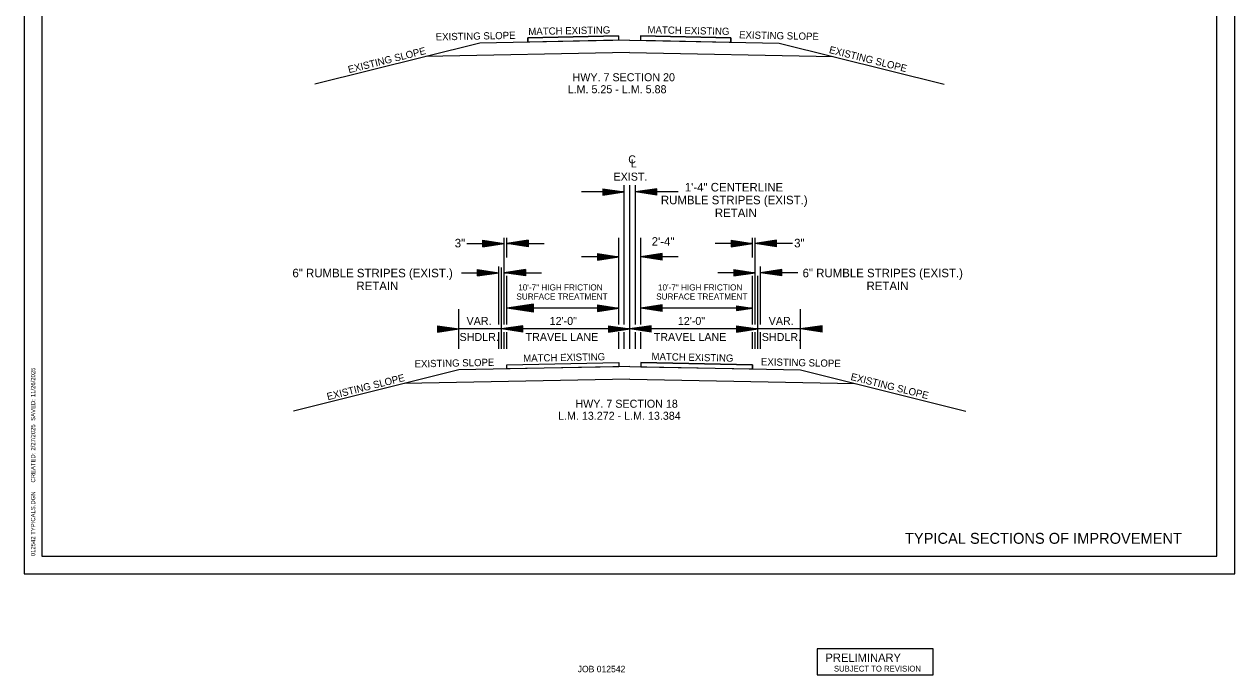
# Model space of a CAD drawing. Extents: x 34757 to 38214, y 51436 to 59430.
# Drawn here: x 34757 to 36457, y 53228 to 54141 of the extents above; entities that cross this region are included whole.
import ezdxf

# ---------------------------------------------------------------- set-up
doc = ezdxf.new("R2010")
doc.units = 0
for name, color, linetype in [('Default', 7, 'Continuous'), ('DSN_DRFT_Junk-No-Plot', 7, 'Continuous'), ('R_Draft', 7, 'Continuous'), ('SHET_Border-Lines', 7, 'Continuous'), ('SHET_Border-Text', 7, 'Continuous')]:
    doc.layers.add(name, color=color, linetype=linetype)

msp = doc.modelspace()

# ---------------------------------------------------------------- linework, layer by layer
at = {"layer": 'Default'}
for p, q in [((35396.6, 54114.9), (35164.6, 54056.9)), ((35606.6, 54119.1), (35396.6, 54114.9)), ((35591.1, 54124.8), (35464.1, 54122.3)), ((35464.1, 54122.3), (35464.1, 54116.3)), ((35606.6, 54119.1), (35816.6, 54114.9)), ((35622.1, 54124.8), (35749.1, 54122.3)), ((35749.1, 54122.3), (35749.1, 54116.3)), ((35816.6, 54114.9), (36048.6, 54056.9)), ((35606.6, 54101.6), (35320.5, 54095.9)), ((35606.6, 54101.6), (35892.7, 54095.9)), ((35569, 53910.4), (35599, 53905.9)), ((35569, 53910.4), (35569, 53901.4)), ((35569, 53909.6), (35594, 53905.9)), ((35569, 53908.8), (35588.8, 53905.9)), ((35569, 53908.1), (35583.8, 53905.9)), ((35569, 53907.3), (35578.7, 53905.9)), ((35599, 53831.9), (35599, 53915.4)), ((35607, 53862.8), (35607, 53915.4)), ((35615, 53831.9), (35615, 53915.4)), ((35645, 53910.4), (35615, 53905.9)), ((35645, 53909.6), (35620, 53905.9)), ((35645, 53908.8), (35625.1, 53905.9)), ((35645, 53908.1), (35630.1, 53905.9)), ((35645, 53907.3), (35635.2, 53905.9)), ((35645, 53901.4), (35645, 53910.4)), ((35599, 53905.9), (35539, 53905.9)), ((35569, 53906.6), (35573.7, 53905.9)), ((35569, 53901.4), (35599, 53905.9)), ((35569, 53904.4), (35578.7, 53905.9)), ((35569, 53902.9), (35588.8, 53905.9)), ((35569, 53902.1), (35594, 53905.9)), ((35569, 53903.6), (35583.8, 53905.9)), ((35569, 53905.1), (35573.7, 53905.9)), ((35645, 53901.4), (35615, 53905.9)), ((35675, 53905.9), (35615, 53905.9)), ((35645, 53902.1), (35620, 53905.9)), ((35645, 53902.9), (35625.1, 53905.9)), ((35645, 53903.6), (35630.1, 53905.9)), ((35645, 53904.4), (35635.2, 53905.9)), ((35645, 53906.6), (35640.2, 53905.9)), ((35645, 53905.1), (35640.2, 53905.9)), ((35607, 53685.5), (35607, 53862.8)), ((35430.7, 53719.7), (35430.7, 53841.5)), ((35434.5, 53813.8), (35434.5, 53841.5)), ((35591.5, 53719.7), (35591.5, 53841.5)), ((35622.5, 53719.7), (35622.5, 53841.5)), ((35779.5, 53813.8), (35779.5, 53841.5)), ((35783.2, 53719.7), (35783.2, 53841.5)), ((35378.2, 53833.5), (35430.7, 53833.5)), ((35400.7, 53838), (35430.7, 53833.5)), ((35400.7, 53829), (35400.7, 53838)), ((35400.7, 53837.2), (35425.7, 53833.5)), ((35400.7, 53836.5), (35420.5, 53833.5)), ((35400.7, 53835.7), (35415.5, 53833.5)), ((35400.7, 53834.9), (35410.5, 53833.5)), ((35400.7, 53834.2), (35405.5, 53833.5)), ((35400.7, 53829), (35430.7, 53833.5)), ((35400.7, 53832), (35410.5, 53833.5)), ((35400.7, 53830.5), (35420.5, 53833.5)), ((35400.7, 53829.7), (35425.7, 53833.5)), ((35400.7, 53831.2), (35415.5, 53833.5)), ((35400.7, 53832.8), (35405.5, 53833.5)), ((35464.5, 53838), (35434.5, 53833.5)), ((35464.5, 53829), (35434.5, 53833.5)), ((35434.5, 53833.5), (35487, 53833.5)), ((35464.5, 53837.2), (35439.5, 53833.5)), ((35464.5, 53829.7), (35439.5, 53833.5)), ((35464.5, 53836.5), (35444.6, 53833.5)), ((35464.5, 53830.5), (35444.6, 53833.5)), ((35464.5, 53835.7), (35449.6, 53833.5)), ((35464.5, 53831.2), (35449.6, 53833.5)), ((35464.5, 53834.9), (35454.7, 53833.5)), ((35464.5, 53832), (35454.7, 53833.5)), ((35464.5, 53834.2), (35459.7, 53833.5)), ((35464.5, 53832.8), (35459.7, 53833.5)), ((35464.5, 53838), (35464.5, 53829)), ((35599, 53719.7), (35599, 53831.9)), ((35615, 53719.7), (35615, 53831.9)), ((35779.5, 53833.5), (35727, 53833.5)), ((35749.5, 53838), (35779.5, 53833.5)), ((35749.5, 53838), (35749.5, 53829)), ((35749.5, 53837.2), (35774.5, 53833.5)), ((35749.5, 53836.5), (35769.3, 53833.5)), ((35749.5, 53835.7), (35764.3, 53833.5)), ((35749.5, 53834.9), (35759.2, 53833.5)), ((35749.5, 53834.2), (35754.2, 53833.5)), ((35749.5, 53829), (35779.5, 53833.5)), ((35749.5, 53832), (35759.2, 53833.5)), ((35749.5, 53830.5), (35769.3, 53833.5)), ((35749.5, 53829.7), (35774.5, 53833.5)), ((35749.5, 53831.2), (35764.3, 53833.5)), ((35749.5, 53832.8), (35754.2, 53833.5)), ((35813.2, 53838), (35783.2, 53833.5)), ((35835.7, 53833.5), (35783.2, 53833.5)), ((35813.2, 53829), (35783.2, 53833.5)), ((35813.2, 53837.2), (35788.2, 53833.5)), ((35813.2, 53829.7), (35788.2, 53833.5)), ((35813.2, 53836.5), (35793.4, 53833.5)), ((35813.2, 53830.5), (35793.4, 53833.5)), ((35813.2, 53835.7), (35798.4, 53833.5)), ((35813.2, 53831.2), (35798.4, 53833.5)), ((35813.2, 53834.9), (35803.5, 53833.5)), ((35813.2, 53832), (35803.5, 53833.5)), ((35813.2, 53834.2), (35808.5, 53833.5)), ((35813.2, 53832.8), (35808.5, 53833.5)), ((35813.2, 53829), (35813.2, 53838)), ((35591.5, 53814.7), (35539, 53814.7)), ((35561.5, 53819.2), (35591.5, 53814.7)), ((35561.5, 53819.2), (35561.5, 53810.2)), ((35561.5, 53818.4), (35586.5, 53814.7)), ((35561.5, 53817.7), (35581.3, 53814.7)), ((35561.5, 53816.9), (35576.3, 53814.7)), ((35561.5, 53816.1), (35571.2, 53814.7)), ((35561.5, 53815.4), (35566.2, 53814.7)), ((35561.5, 53810.2), (35591.5, 53814.7)), ((35561.5, 53813.2), (35571.2, 53814.7)), ((35561.5, 53811.7), (35581.3, 53814.7)), ((35561.5, 53810.9), (35586.5, 53814.7)), ((35561.5, 53812.5), (35576.3, 53814.7)), ((35561.5, 53814), (35566.2, 53814.7)), ((35652.5, 53819.2), (35622.5, 53814.7)), ((35675, 53814.7), (35622.5, 53814.7)), ((35652.5, 53810.2), (35622.5, 53814.7)), ((35652.5, 53818.4), (35627.5, 53814.7)), ((35652.5, 53810.9), (35627.5, 53814.7)), ((35652.5, 53817.7), (35632.6, 53814.7)), ((35652.5, 53811.7), (35632.6, 53814.7)), ((35652.5, 53816.9), (35637.6, 53814.7)), ((35652.5, 53812.5), (35637.6, 53814.7)), ((35652.5, 53816.2), (35642.7, 53814.7)), ((35652.5, 53813.2), (35642.7, 53814.7)), ((35652.5, 53815.4), (35647.7, 53814.7)), ((35652.5, 53814), (35647.7, 53814.7)), ((35652.5, 53810.2), (35652.5, 53819.2)), ((35370.7, 53792.4), (35423.2, 53792.4)), ((35393.2, 53796.9), (35423.2, 53792.4)), ((35393.2, 53787.9), (35393.2, 53796.9)), ((35393.2, 53796.2), (35418.2, 53792.4)), ((35393.2, 53795.4), (35413, 53792.4)), ((35393.2, 53794.7), (35408, 53792.4)), ((35393.2, 53793.9), (35403, 53792.4)), ((35393.2, 53793.1), (35398, 53792.4)), ((35393.2, 53787.9), (35423.2, 53792.4)), ((35393.2, 53791), (35403, 53792.4)), ((35393.2, 53789.5), (35413, 53792.4)), ((35393.2, 53788.7), (35418.2, 53792.4)), ((35393.2, 53790.2), (35408, 53792.4)), ((35393.2, 53791.7), (35398, 53792.4)), ((35423.2, 53719.7), (35423.2, 53801)), ((35427, 53685.5), (35427, 53799.9)), ((35427, 53685.5), (35427, 53788)), ((35460.7, 53796.9), (35430.7, 53792.4)), ((35460.7, 53787.9), (35430.7, 53792.4)), ((35430.7, 53792.4), (35483.2, 53792.4)), ((35434.5, 53719.7), (35434.5, 53788.2)), ((35460.7, 53796.2), (35435.7, 53792.4)), ((35460.7, 53788.7), (35435.7, 53792.4)), ((35460.7, 53795.4), (35440.9, 53792.4)), ((35460.7, 53789.5), (35440.9, 53792.4)), ((35460.7, 53794.7), (35445.9, 53792.4)), ((35460.7, 53790.2), (35445.9, 53792.4)), ((35460.7, 53793.9), (35451, 53792.4)), ((35460.7, 53791), (35451, 53792.4)), ((35460.7, 53793.1), (35456, 53792.4)), ((35460.7, 53791.7), (35456, 53792.4)), ((35460.7, 53796.9), (35460.7, 53787.9)), ((35783.2, 53792.4), (35730.7, 53792.4)), ((35753.2, 53796.9), (35783.2, 53792.4)), ((35753.2, 53796.9), (35753.2, 53787.9)), ((35753.2, 53796.2), (35778.2, 53792.4)), ((35753.2, 53795.4), (35773, 53792.4)), ((35753.2, 53794.7), (35768, 53792.4)), ((35753.2, 53793.9), (35763, 53792.4)), ((35753.2, 53793.1), (35758, 53792.4)), ((35753.2, 53787.9), (35783.2, 53792.4)), ((35753.2, 53791), (35763, 53792.4)), ((35753.2, 53789.5), (35773, 53792.4)), ((35753.2, 53788.7), (35778.2, 53792.4)), ((35753.2, 53790.2), (35768, 53792.4)), ((35753.2, 53791.7), (35758, 53792.4)), ((35779.5, 53719.7), (35779.5, 53788.2)), ((35787, 53685.5), (35787, 53788)), ((35790.7, 53719.7), (35790.7, 53801)), ((35820.7, 53796.9), (35790.7, 53792.4)), ((35820.7, 53787.9), (35790.7, 53792.4)), ((35843.2, 53792.4), (35790.7, 53792.4)), ((35820.7, 53796.2), (35795.7, 53792.4)), ((35820.7, 53788.7), (35795.7, 53792.4)), ((35820.7, 53795.4), (35800.9, 53792.4)), ((35820.7, 53789.5), (35800.9, 53792.4)), ((35820.7, 53794.7), (35805.9, 53792.4)), ((35820.7, 53790.2), (35805.9, 53792.4)), ((35820.7, 53793.9), (35811, 53792.4)), ((35820.7, 53791), (35811, 53792.4)), ((35820.7, 53793.1), (35816, 53792.4)), ((35820.7, 53791.7), (35816, 53792.4)), ((35820.7, 53787.9), (35820.7, 53796.9)), ((35367, 53685.5), (35367, 53741.5)), ((35472, 53748.3), (35434.5, 53742.7)), ((35591.5, 53742.7), (35434.5, 53742.7)), ((35472, 53737), (35434.5, 53742.7)), ((35472, 53747.4), (35440.7, 53742.7)), ((35472, 53738), (35440.7, 53742.7)), ((35472, 53746.4), (35447.2, 53742.7)), ((35472, 53738.9), (35447.2, 53742.7)), ((35472, 53745.5), (35453.4, 53742.7)), ((35472, 53739.9), (35453.4, 53742.7)), ((35472, 53744.5), (35459.8, 53742.7)), ((35472, 53740.9), (35459.8, 53742.7)), ((35472, 53743.6), (35466, 53742.7)), ((35472, 53741.8), (35466, 53742.7)), ((35472, 53737), (35472, 53748.3)), ((35561.5, 53747.2), (35591.5, 53742.7)), ((35561.5, 53747.2), (35561.5, 53738.2)), ((35561.5, 53746.4), (35586.5, 53742.7)), ((35561.5, 53745.7), (35581.3, 53742.7)), ((35561.5, 53744.9), (35576.3, 53742.7)), ((35561.5, 53744.1), (35571.2, 53742.7)), ((35561.5, 53743.4), (35566.2, 53742.7)), ((35561.5, 53738.2), (35591.5, 53742.7)), ((35561.5, 53741.2), (35571.2, 53742.7)), ((35561.5, 53739.7), (35581.3, 53742.7)), ((35561.5, 53738.9), (35586.5, 53742.7)), ((35561.5, 53740.4), (35576.3, 53742.7)), ((35561.5, 53742), (35566.2, 53742.7)), ((35652.5, 53747.2), (35622.5, 53742.7)), ((35779.5, 53742.7), (35622.5, 53742.7)), ((35652.5, 53738.2), (35622.5, 53742.7)), ((35652.5, 53746.4), (35627.5, 53742.7)), ((35652.5, 53738.9), (35627.5, 53742.7)), ((35652.5, 53745.7), (35632.6, 53742.7)), ((35652.5, 53739.7), (35632.6, 53742.7)), ((35652.5, 53744.9), (35637.6, 53742.7)), ((35652.5, 53740.4), (35637.6, 53742.7)), ((35652.5, 53744.1), (35642.7, 53742.7)), ((35652.5, 53741.2), (35642.7, 53742.7)), ((35652.5, 53743.4), (35647.7, 53742.7)), ((35652.5, 53742), (35647.7, 53742.7)), ((35652.5, 53738.2), (35652.5, 53747.2)), ((35757, 53746), (35779.5, 53742.7)), ((35757, 53746), (35757, 53739.3)), ((35757, 53745.5), (35775.7, 53742.7)), ((35757, 53744.9), (35771.8, 53742.7)), ((35757, 53744.3), (35768.1, 53742.7)), ((35757, 53743.8), (35764.3, 53742.7)), ((35757, 53743.2), (35760.5, 53742.7)), ((35757, 53739.3), (35779.5, 53742.7)), ((35757, 53741.6), (35764.3, 53742.7)), ((35757, 53740.4), (35771.8, 53742.7)), ((35757, 53739.9), (35775.7, 53742.7)), ((35757, 53741), (35768.1, 53742.7)), ((35757, 53742.1), (35760.5, 53742.7)), ((35847, 53685.5), (35847, 53741.5)), ((35337, 53718), (35367, 53713.5)), ((35337, 53718), (35337, 53709)), ((35337, 53717.2), (35362, 53713.5)), ((35337, 53716.5), (35356.8, 53713.5)), ((35337, 53715.7), (35351.8, 53713.5)), ((35337, 53714.9), (35346.7, 53713.5)), ((35337, 53714.2), (35341.7, 53713.5)), ((35337, 53709), (35367, 53713.5)), ((35337, 53712), (35346.7, 53713.5)), ((35337, 53710.5), (35356.8, 53713.5)), ((35337, 53709.7), (35362, 53713.5)), ((35337, 53711.2), (35351.8, 53713.5)), ((35337, 53712.8), (35341.7, 53713.5)), ((35427, 53713.5), (35367, 53713.5)), ((35423.2, 53685.5), (35423.2, 53709.1)), ((35457, 53718), (35427, 53713.5)), ((35607, 53713.5), (35427, 53713.5)), ((35457, 53709), (35427, 53713.5)), ((35430.7, 53685.5), (35430.7, 53709.1)), ((35457, 53717.2), (35432, 53713.5)), ((35457, 53709.7), (35432, 53713.5)), ((35434.5, 53685.5), (35434.5, 53709.1)), ((35457, 53716.5), (35437.1, 53713.5)), ((35457, 53710.5), (35437.1, 53713.5)), ((35457, 53715.7), (35442.1, 53713.5)), ((35457, 53711.2), (35442.1, 53713.5)), ((35457, 53714.9), (35447.2, 53713.5)), ((35457, 53712), (35447.2, 53713.5)), ((35457, 53714.2), (35452.2, 53713.5)), ((35457, 53712.8), (35452.2, 53713.5)), ((35457, 53709), (35457, 53718)), ((35577, 53718), (35607, 53713.5)), ((35577, 53718), (35577, 53709)), ((35577, 53717.2), (35602, 53713.5)), ((35577, 53716.5), (35596.8, 53713.5)), ((35577, 53715.7), (35591.8, 53713.5)), ((35577, 53714.9), (35586.7, 53713.5)), ((35577, 53714.2), (35581.7, 53713.5)), ((35577, 53709), (35607, 53713.5)), ((35577, 53712), (35586.7, 53713.5)), ((35577, 53710.5), (35596.8, 53713.5)), ((35577, 53709.7), (35602, 53713.5)), ((35577, 53711.2), (35591.8, 53713.5)), ((35577, 53712.8), (35581.7, 53713.5)), ((35591.5, 53685.5), (35591.5, 53709.1)), ((35599, 53685.5), (35599, 53709.1)), ((35637, 53718), (35607, 53713.5)), ((35787, 53713.5), (35607, 53713.5)), ((35637, 53709), (35607, 53713.5)), ((35637, 53717.2), (35612, 53713.5)), ((35637, 53709.7), (35612, 53713.5)), ((35615, 53685.5), (35615, 53709.1)), ((35637, 53716.5), (35617.1, 53713.5)), ((35637, 53710.5), (35617.1, 53713.5)), ((35637, 53715.7), (35622.1, 53713.5)), ((35637, 53711.2), (35622.1, 53713.5)), ((35622.5, 53685.5), (35622.5, 53709.1)), ((35637, 53714.9), (35627.2, 53713.5)), ((35637, 53712), (35627.2, 53713.5)), ((35637, 53714.2), (35632.2, 53713.5)), ((35637, 53712.8), (35632.2, 53713.5)), ((35637, 53709), (35637, 53718)), ((35757, 53718), (35787, 53713.5)), ((35757, 53718), (35757, 53709)), ((35757, 53717.2), (35782, 53713.5)), ((35757, 53716.5), (35776.8, 53713.5)), ((35757, 53715.7), (35771.8, 53713.5)), ((35757, 53714.9), (35766.7, 53713.5)), ((35757, 53714.2), (35761.7, 53713.5)), ((35757, 53709), (35787, 53713.5)), ((35757, 53712), (35766.7, 53713.5)), ((35757, 53710.5), (35776.8, 53713.5)), ((35757, 53709.7), (35782, 53713.5)), ((35757, 53711.2), (35771.8, 53713.5)), ((35757, 53712.8), (35761.7, 53713.5)), ((35779.5, 53685.5), (35779.5, 53709.1)), ((35783.2, 53685.5), (35783.2, 53709.1)), ((35847, 53713.5), (35787, 53713.5)), ((35790.7, 53685.5), (35790.7, 53709.1)), ((35877, 53718), (35847, 53713.5)), ((35877, 53709), (35847, 53713.5)), ((35877, 53717.2), (35852, 53713.5)), ((35877, 53709.7), (35852, 53713.5)), ((35877, 53716.5), (35857.1, 53713.5)), ((35877, 53710.5), (35857.1, 53713.5)), ((35877, 53715.7), (35862.1, 53713.5)), ((35877, 53711.2), (35862.1, 53713.5)), ((35877, 53714.9), (35867.2, 53713.5)), ((35877, 53712), (35867.2, 53713.5)), ((35877, 53714.2), (35872.2, 53713.5)), ((35877, 53712.8), (35872.2, 53713.5)), ((35877, 53709), (35877, 53718)), ((35367, 53655.9), (35135, 53597.9)), ((35607, 53660.7), (35367, 53655.9)), ((35607, 53660.7), (35847, 53655.9)), ((35622.5, 53666.4), (35779.5, 53663.3)), ((35779.5, 53663.3), (35779.5, 53657.3)), ((35847, 53655.9), (36079, 53597.9)), ((35607, 53643.2), (35290.9, 53636.9)), ((35607, 53643.2), (35923.1, 53636.9))]:
    msp.add_line(p, q, dxfattribs=at)
for points in [[(34756.6, 54469.6), (34756.6, 53369.6), (36456.6, 53369.6), (36456.6, 54469.6)], [(35591.1, 54124.8), (35591.1, 54118.8), (35591.1, 54118.8), (35464.1, 54116.3), (35464.1, 54122.3), (35591.1, 54124.8)], [(35622.1, 54124.8), (35622.1, 54118.8), (35622.1, 54118.8), (35749.1, 54116.3), (35749.1, 54122.3), (35622.1, 54124.8)], [(35591.5, 53666.4), (35591.5, 53660.4), (35591.5, 53660.4), (35434.5, 53657.3), (35434.5, 53663.3), (35591.5, 53666.4)], [(35622.5, 53666.4), (35622.5, 53660.4), (35622.5, 53660.4), (35779.5, 53657.3), (35779.5, 53663.3), (35622.5, 53666.4)], [(35870.2, 53228), (36033.2, 53228), (36033.2, 53264.4), (35870.2, 53264.4)]]:
    msp.add_lwpolyline(points, close=True, dxfattribs=at)
at = {"layer": 'DSN_DRFT_Junk-No-Plot'}
msp.add_lwpolyline([(34756.6, 54469.6), (34756.6, 53369.6), (36456.6, 53369.6), (36456.6, 54469.6)], close=True, dxfattribs=at)
at = {"layer": 'SHET_Border-Lines'}
for points in [[(34756.6, 53369.6), (36456.6, 53369.6), (36456.6, 54469.6), (34756.6, 54469.6)], [(34781.6, 53394.6), (36431.6, 53394.6), (36431.6, 54444.6), (34781.6, 54444.6)]]:
    msp.add_lwpolyline(points, close=True, dxfattribs=at)

# ---------------------------------------------------------------- texts
at = {"layer": 'Default'}
for s, rotation, p in [('EXISTING SLOPE', 1.2244, (35334.6, 54118.4)), ('MATCH EXISTING', 1.146, (35464.6, 54126)), ('MATCH EXISTING', 358.7756, (35631.8, 54128.6)), ('EXISTING SLOPE', 358.7756, (35760.4, 54121.4)), ('EXISTING SLOPE', 14.0368, (35212.7, 54072.4)), ('EXISTING SLOPE', 345.9632, (35886.2, 54101)), ('EXISTING SLOPE', 1.2244, (35304.9, 53659.4)), ('MATCH EXISTING', 1.146, (35457.4, 53667.3)), ('MATCH EXISTING', 358.7756, (35637.4, 53669.9)), ('EXISTING SLOPE', 358.7756, (35791.1, 53662.4)), ('EXISTING SLOPE', 14.0368, (35183, 53613.4)), ('EXISTING SLOPE', 345.9632, (35916.5, 53642))]:
    msp.add_text(s, height=10.125, rotation=rotation, dxfattribs=at).set_placement(p)
for s, height, p in [('HWY. 7 SECTION 20', 11.25, (35526.7, 54061.2)), ('L.M. 5.25 - L.M. 5.88', 11.25, (35519.8, 54044.4)), ('C', 11.2, (35604.9, 53946)), ('L', 11.2, (35608.3, 53940.3)), ('EXIST.', 11.24, (35584.2, 53921.7)), ('1\'-4" CENTERLINE ', 12.007, (35684.3, 53906.5)), ('RUMBLE STRIPES (EXIST.) ', 12.007, (35650.7, 53888.5)), ('RETAIN', 12.01, (35726.5, 53870.5)), ('3"', 12.01, (35361.2, 53828)), ('2\'-4"', 12.01, (35637.8, 53830.3)), ('3"', 12.01, (35837.9, 53828)), ('6" RUMBLE STRIPES (EXIST.) ', 12.007, (35133.3, 53786)), ('6" RUMBLE STRIPES (EXIST.) ', 12.007, (35849.7, 53786)), ('RETAIN', 12.01, (35223.1, 53768)), ('10\'-7" HIGH FRICTION', 8.581, (35450.4, 53767.5)), ('10\'-7" HIGH FRICTION', 8.581, (35646.6, 53767.5)), ('RETAIN', 12.01, (35939.5, 53768)), ('SURFACE TREATMENT', 8.581, (35447.8, 53754.7)), ('SURFACE TREATMENT', 8.581, (35644.1, 53754.7)), ('VAR.', 11.25, (35377.8, 53719.1)), ('12\'-0"', 11.25, (35494.5, 53719.1)), ('12\'-0"', 11.25, (35674.5, 53719.1)), ('VAR.', 11.25, (35802.1, 53719.1)), ('SHDLR.', 11.25, (35368, 53696.6)), ('TRAVEL LANE', 11.25, (35460.7, 53696.6)), ('TRAVEL LANE', 11.25, (35640.7, 53696.6)), ('SHDLR.', 11.25, (35792.4, 53696.6)), ('HWY. 7 SECTION 18', 11.25, (35530.7, 53602.9)), ('L.M. 13.272 - L.M. 13.384', 11.25, (35506.3, 53586)), ('TYPICAL SECTIONS OF IMPROVEMENT', 15.349, (35993.5, 53411.9)), ('PRELIMINARY', 11.7, (35881.8, 53246.2)), ('SUBJECT TO REVISION', 8.1, (35893.7, 53232.6))]:
    msp.add_text(s, height=height, dxfattribs=at).set_placement(p)
at = {"layer": 'R_Draft'}
msp.add_text('JOB 012542', height=9, dxfattribs=at).set_placement((35533.9, 53231.6))
at = {"layer": 'SHET_Border-Text'}
for s, p in [('11/26/2025', (34772.1, 53617.8)), ('  SAVED: ', (34772.1, 53580)), ('2/27/2025', (34772.1, 53542.7)), ('     CREATED: ', (34772.1, 53486.4)), ('012542 TYPICALS.DGN', (34772.1, 53394.6))]:
    msp.add_text(s, height=6, rotation=90, dxfattribs=at).set_placement(p)

doc.saveas('drawing.dxf')
